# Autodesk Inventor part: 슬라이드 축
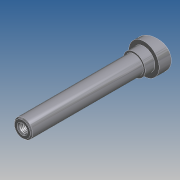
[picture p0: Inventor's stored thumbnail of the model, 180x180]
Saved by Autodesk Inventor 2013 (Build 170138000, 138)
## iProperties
Company: 한국ATC센터
Created: 2014-07
Part Number: 슬라이드 축
Document SubType Name: 모델링
Designer: KYOUNG IL JANG
Mass: 19.8501 g
Surface Area: 63.0734 cm^2
Volume: 19.8501 cm^3
Density: 1 g/cm^3
Material: 강철, 연강
변환 표준: STEP AP214IS
파일 이름: C:\Users\SeoGD\Desktop\?쒗뿕\異?stp
전처리기: Build: 253, Release: 2010 SP1 - Date: Wed 07/29/2009
전송 단위: 밀리미터
불확실성: 0.01
Author: KYOUNG IL JANG
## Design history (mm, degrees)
sketch "스케치1"
  geometry: L1 (0, 100)-(7.5, 100); L2 (7.5, 100)-(7.5, 0); L3 (7.5, 0)-(12.5, 0); L4 (12.5, 0)-(12.5, -17); L5 (12.5, -17)-(0, -17); L6 (0, -17)-(0, 100); 1 further point
  constraints: 12 end point, 2 parallel, 2 point on line, 1 perpendicular, 1 vertical
  dimensions: "d0" = 100 distance from line of L1 point (0, 0); "d1" = 15 diameter of L2 L6; "d2" = 25 diameter of L4 L6; "d3" = 17 distance of L3.end L4.end
revolve "회전1" sketch "스케치1" stored, may be unused: angle "d4" = 90 deg
sketch "스케치2"
  geometry: L1 (12.5, 0)-(12.5, -17) reference; L2 (-12.5, -17)-(12.5, -17) reference; L3 (-12.5, 0)-(-12.5, -17) reference; L4 (12.5, -5)-(-12.5, -11.699); L5 (-12.5, 0)-(12.5, 0) reference; 1 further point
  constraints: 2 end point, 2 point on line
  dimensions: "d5" = 75 deg angle of L1 L4; "d6" = 5 distance from line of L4.start L5
extrude "돌출1" cut sketch "스케치2" stored distance "d7" = 10; taper "d8" = 0 deg
chamfer "모따기1" distance "d9" = 1; stored, may be unused: second distance "d10" = 2, angle "d11" = 45 deg
fillet "모깎기1" dims "d12" = 0.5
hole "구멍1" diameter "d15" = 6.647; stored, may be unused: countersink angle "d19" = 90 deg, drill point angle "d21" = 118 deg; dims "d13" = 10, "d14" = 10, "d16" = 17, "d17" = 4, "d18" = 2, "d20" = 20
chamfer "모따기2" distance "d22" = 1; stored, may be unused: second distance "d23" = 2, angle "d24" = 45 deg
sketch "스케치3"
  geometry: C1 r 9 at (0, 0); 1 further point
  constraints: 1 centre point, 1 coincident
  dimensions: "d25" = 18 diameter of C1
extrude "돌출2" join sketch "스케치3" distance "d26" = 8; taper "d27" = 0 deg
node "솔리드1"
node "솔리드 본체"
node "곡면 본체"
node "솔리드2"
